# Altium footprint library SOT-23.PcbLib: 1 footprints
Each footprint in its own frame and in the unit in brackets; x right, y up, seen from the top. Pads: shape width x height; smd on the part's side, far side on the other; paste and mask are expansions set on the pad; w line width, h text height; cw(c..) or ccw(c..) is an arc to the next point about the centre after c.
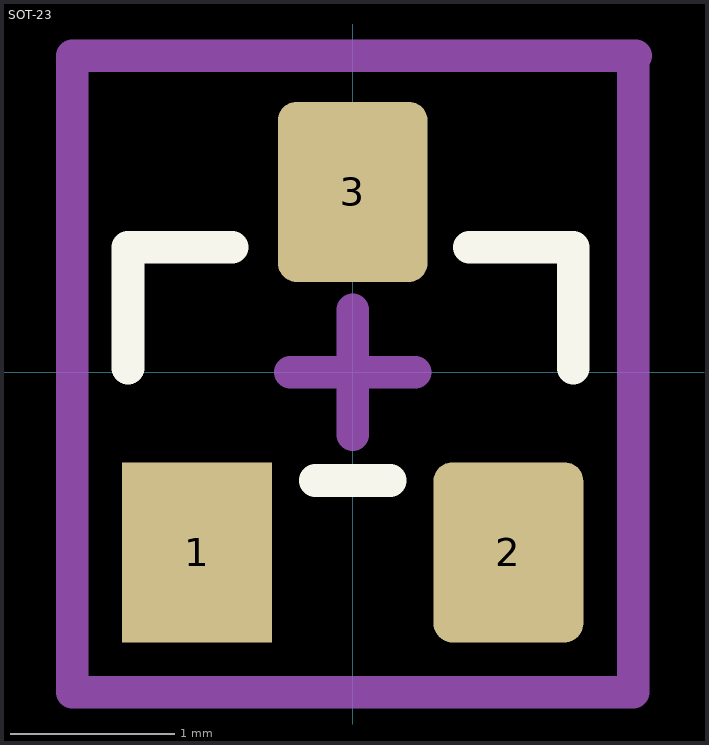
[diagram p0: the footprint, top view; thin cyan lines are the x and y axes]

## SOT-23 [mm] "3mm x 2.64"
height 1.12
pads (3):
  rect 0.914x1.1 smd: 1(-0.95,-1.1)
  rrect25% 0.914x1.1 smd: 2(0.95,-1.1) 3(0,1.1)
Top Overlay:
  lines w0.2: -1.372,0.025 -1.372,0.762 -0.737,0.762 ; -0.229,-0.66 0.229,-0.66 ; 0.711,0.762 1.346,0.762 1.346,0.025
Mechanical 15:
  lines w0.2: -1.712,1.93 -1.712,-1.953 -1.712,-1.953 1.712,-1.953 1.712,1.93 ; -1.699,1.93 1.728,1.93 ; -0.381,0 0.381,0 ; 0,-0.381 0,0.381
3D body "User Library-SOT23-3.STEP": height 1.3, standoff 0, extent -1.45,-1.4 1.45,1.4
